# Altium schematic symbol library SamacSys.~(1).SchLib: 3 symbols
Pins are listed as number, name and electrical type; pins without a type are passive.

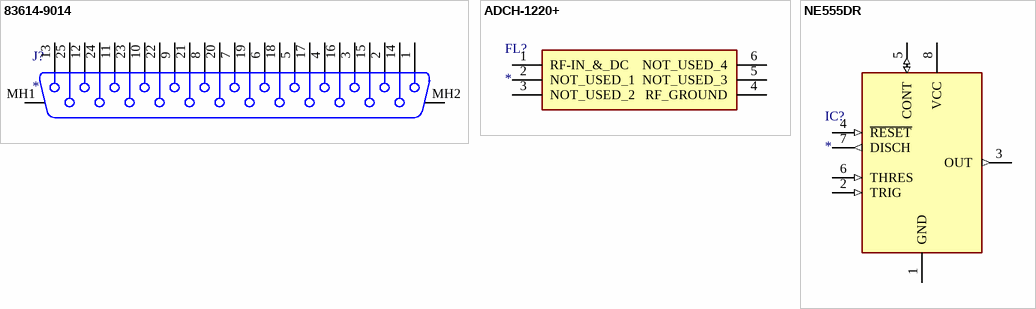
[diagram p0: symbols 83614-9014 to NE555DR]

## 83614-9014
designator J?
Connector; Manufacturer_Name: Molex; Manufacturer_Part_Number: 83614-9014
footprint 836149014
pins: 1, 2, 3, 4, 5, 6, 7, 8, 9, 10, 11, 12, 13, 14, 15, 16, 17, 18, 19, 20, 21, 22, 23, 24, 25, MH1, MH2

## ADCH-1220+
designator FL?
Filter; Manufacturer_Name: Mini-Circuits; Manufacturer_Part_Number: ADCH-1220+
footprint ADCH1220
pins: 1 RF-IN_&_DC, 2 NOT_USED_1, 3 NOT_USED_2, 4 RF_GROUND, 5 NOT_USED_3, 6 NOT_USED_4

## NE555DR
designator IC?
Integrated Circuit; Manufacturer_Name: Texas Instruments; Manufacturer_Part_Number: NE555DR
footprint SOIC127P600X175-8N
pins: 1 GND (power), 2 TRIG (in), 3 OUT (out), 4 ~{RESET} (in), 5 CONT (io), 6 THRES (in), 7 DISCH (out), 8 VCC (power)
